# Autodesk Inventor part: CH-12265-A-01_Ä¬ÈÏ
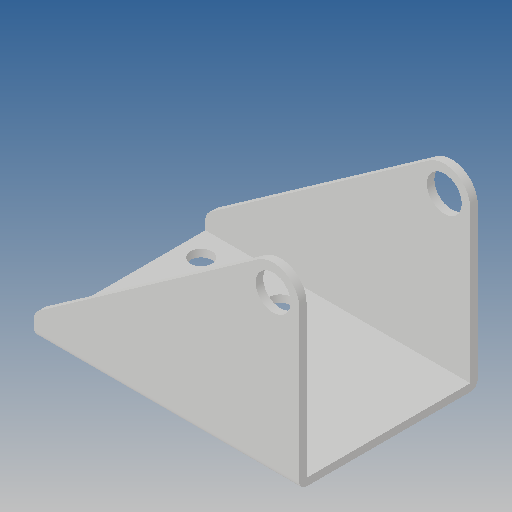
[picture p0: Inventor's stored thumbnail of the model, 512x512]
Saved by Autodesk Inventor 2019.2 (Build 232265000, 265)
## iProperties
Created: 2010-06
Part Number: CH-12265-A-01_Ä¬ÈÏ
Material: Ogólny
Document SubType Name: Modeling
Designer: CADENGINEERING4
Density: 1 g/cm^3
Appearance: Domyślna
Author: CADENGINEERING4
Revision Number: ÈÎºÎ
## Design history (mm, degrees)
feature "NONE"
node "Bryła1"
